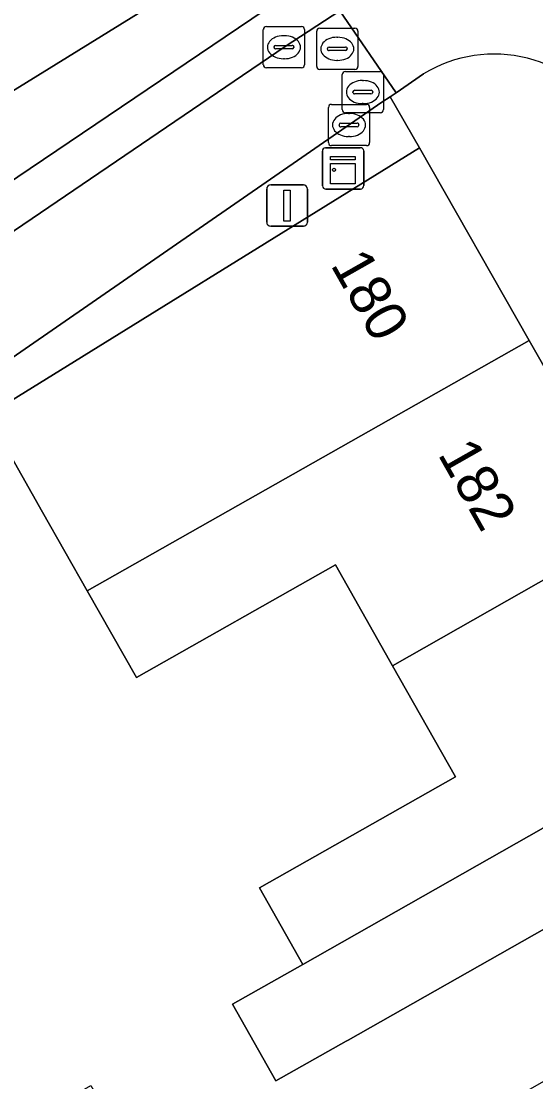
# Model space of a CAD drawing. Extents: x 159888 to 160761, y 384031 to 384750.
# Drawn here: x 160476.49 to 160488.98, y 384308.57 to 384334.29 of the extents above; entities that cross this region are included whole.
import ezdxf

# ---------------------------------------------------------------- set-up
doc = ezdxf.new("R2010")
doc.units = 0
for name, color, linetype in [('IMGEO_Erf', 7, 'Continuous'), ('IMGEO_Kast', 7, 'Continuous'), ('IMGEO_Kolk', 7, 'Continuous'), ('IMGEO_Lichtmast', 7, 'Continuous'), ('IMGEO_Pand', 7, 'Continuous'), ('IMGEO_Pand_nummerreeks', 7, 'Continuous'), ('IMGEO_Rijbaan_lokaal_open', 7, 'Continuous'), ('IMGEO_Rioolput', 7, 'Continuous'), ('IMGEO_Voetpad_open', 7, 'Continuous')]:
    doc.layers.add(name, color=color, linetype=linetype)

msp = doc.modelspace()

# ---------------------------------------------------------------- linework, layer by layer
at = {"layer": 'IMGEO_Erf'}
for points in [[(160456.666, 384356.276), (160458.578, 384353.848), (160460.552, 384351.342), (160461.672, 384352.224), (160468.506, 384356.754), (160471.872, 384351.597), (160475.173, 384346.539), (160478.474, 384341.481), (160481.974, 384336.119), (160475.071, 384331.85), (160475.896, 384330.595), (160472.553, 384328.397), (160468.334, 384334.813), (160471.677, 384337.011), (160468.359, 384342.057), (160465.04, 384347.104), (160461.502, 384344.777), (160458.334, 384349.595), (160454.817, 384346.825), (160452.803, 384349.382), (160452.769, 384349.425), (160446.476, 384344.469), (160444.638, 384346.803)], [(160487.032, 384315.964), (160485.504, 384318.66), (160484.117, 384321.107), (160479.288, 384318.371), (160478.097, 384320.473), (160477.012, 384322.387), (160475.678, 384324.741), (160470.773, 384321.422), (160473.178, 384317.676), (160469.475, 384315.595), (160472.079, 384311.028), (160474.675, 384306.475), (160478.184, 384308.475), (160480.847, 384303.804), (160490.773, 384309.494), (160489.194, 384312.28), (160484.426, 384309.578), (160484.38, 384309.552), (160482.675, 384308.586), (160481.62, 384310.447), (160483.325, 384311.413), (160482.275, 384313.267)]]:
    msp.add_lwpolyline(points, close=True, dxfattribs=at)
msp.add_lwpolyline([(160434.938, 384346.488), (160443.918, 384333.117), (160448.156, 384336.03), (160449.423, 384334.187), (160445.166, 384331.26), (160449.784, 384324.384), (160456.397, 384328.826), (160459.01, 384330.581), (160461.626, 384332.337), (160462.527, 384330.994), (160464.329, 384332.179), (160467.485, 384327.479), (160463.08, 384324.521), (160460.466, 384322.766), (160461.863, 384320.697), (160467.03, 384324.187), (160476.088, 384330.303), (160483.657, 384335.415)], dxfattribs=at)
at = {"layer": 'IMGEO_Kast'}
for p, q in [((160483.88, 384331.223), (160484.721, 384331.223)), ((160484.721, 384331.223), (160483.88, 384331.223)), ((160483.805, 384330.298), (160483.805, 384331.139)), ((160483.805, 384331.139), (160483.805, 384330.298)), ((160484.805, 384331.148), (160484.805, 384330.307)), ((160484.805, 384330.307), (160484.805, 384331.148)), ((160484.73, 384330.223), (160483.889, 384330.223)), ((160483.889, 384330.223), (160484.73, 384330.223))]:
    msp.add_line(p, q, dxfattribs=at)
for points in [[(160484, 384331.013), (160484.6, 384331.013), (160484.6, 384330.928), (160484, 384330.928), (160484, 384331.013)], [(160484, 384330.838), (160484.6, 384330.838), (160484.6, 384330.349), (160484, 384330.349), (160484, 384330.838)]]:
    msp.add_lwpolyline(points, dxfattribs=at)
msp.add_circle((160484.084, 384330.687), 0.0377, dxfattribs=at)
for centre, start, end in [((160483.883, 384331.145), 92.4484, 184.2845), ((160483.883, 384331.145), 92.4484, 184.2845), ((160484.727, 384331.145), 2.4484, 94.2845), ((160484.727, 384331.145), 2.4484, 94.2845), ((160483.883, 384330.301), 182.4484, 274.2845), ((160483.883, 384330.301), 182.4484, 274.2845), ((160484.727, 384330.301), 272.4484, 4.2845), ((160484.727, 384330.301), 272.4484, 4.2845)]:
    msp.add_arc(centre, 0.0779, start, end, dxfattribs=at)
at = {"layer": 'IMGEO_Kolk'}
for p, q in [((160482.369, 384333.237), (160482.369, 384334.089)), ((160482.444, 384334.163), (160483.296, 384334.163)), ((160483.37, 384334.089), (160483.37, 384333.237)), ((160482.857, 384333.943), (160482.882, 384333.943)), ((160482.628, 384333.657), (160482.628, 384333.669)), ((160483.066, 384333.62), (160482.668, 384333.62)), ((160482.671, 384333.706), (160483.069, 384333.706)), ((160483.112, 384333.669), (160483.112, 384333.657)), ((160482.88, 384333.383), (160482.855, 384333.383)), ((160483.296, 384333.163), (160482.444, 384333.163)), ((160484.023, 384332.276), (160484.875, 384332.276)), ((160483.948, 384331.35), (160483.948, 384332.202)), ((160484.436, 384332.056), (160484.461, 384332.056)), ((160484.949, 384332.202), (160484.949, 384331.35)), ((160484.207, 384331.77), (160484.207, 384331.782)), ((160484.645, 384331.733), (160484.247, 384331.733)), ((160484.25, 384331.819), (160484.648, 384331.819)), ((160484.691, 384331.782), (160484.691, 384331.77)), ((160484.459, 384331.496), (160484.434, 384331.496)), ((160484.875, 384331.276), (160484.023, 384331.276))]:
    msp.add_line(p, q, dxfattribs=at)
for points in [[(160482.369, 384333.237), (160482.369, 384334.089)], [(160482.444, 384334.163), (160483.296, 384334.163)], [(160483.37, 384334.089), (160483.37, 384333.237)], [(160483.296, 384333.163), (160482.444, 384333.163)], [(160484.023, 384332.276), (160484.875, 384332.276)], [(160483.948, 384331.35), (160483.948, 384332.202)], [(160484.949, 384332.202), (160484.949, 384331.35)], [(160484.875, 384331.276), (160484.023, 384331.276)]]:
    msp.add_lwpolyline(points, dxfattribs=at)
for centre, radius, start, end in [((160482.446, 384334.087), 0.0765, 91.552, 178.448), ((160482.446, 384334.087), 0.0765, 91.552, 178.448), ((160483.294, 384334.087), 0.0765, 1.552, 88.448), ((160483.294, 384334.087), 0.0765, 1.552, 88.448), ((160482.668, 384333.666), 0.0403, 85.8775, 175.7526), ((160482.665, 384333.656), 0.0366, 178.938, 274.7102), ((160483.069, 384333.663), 0.043, 264.8664, 352.4533), ((160483.073, 384333.668), 0.0386, 1.7309, 96.639), ((160482.446, 384333.239), 0.0765, 181.552, 268.448), ((160482.446, 384333.239), 0.0765, 181.552, 268.448), ((160483.294, 384333.239), 0.0765, 271.552, 358.448), ((160483.294, 384333.239), 0.0765, 271.552, 358.448), ((160484.025, 384332.2), 0.0765, 91.552, 178.448), ((160484.025, 384332.2), 0.0765, 91.552, 178.448), ((160484.873, 384332.2), 0.0765, 1.552, 88.448), ((160484.873, 384332.2), 0.0765, 1.552, 88.448), ((160484.247, 384331.779), 0.0403, 85.8775, 175.7526), ((160484.244, 384331.769), 0.0366, 178.938, 274.7102), ((160484.648, 384331.776), 0.043, 264.8664, 352.4533), ((160484.652, 384331.781), 0.0386, 1.7309, 96.639), ((160484.025, 384331.352), 0.0765, 181.552, 268.448), ((160484.025, 384331.352), 0.0765, 181.552, 268.448), ((160484.873, 384331.352), 0.0765, 271.552, 358.448), ((160484.873, 384331.352), 0.0765, 271.552, 358.448)]:
    msp.add_arc(centre, radius, start, end, dxfattribs=at)
for centre, major_axis, ratio, start_param, end_param in [((160482.856, 384333.663), (-0.387, 0.002), 0.722429, 4.712389, 7.853982), ((160482.881, 384333.663), (-0.39, 0.002), 0.717154, 1.570796, 4.712389), ((160484.435, 384331.776), (-0.387, 0.002), 0.722429, 4.712389, 7.853982), ((160484.46, 384331.776), (-0.39, 0.002), 0.717154, 1.570796, 4.712389)]:
    msp.add_ellipse(centre, major_axis=major_axis, ratio=ratio, start_param=start_param, end_param=end_param, dxfattribs=at)
at = {"layer": 'IMGEO_Lichtmast'}
for p, q in [((160482.45, 384329.421), (160482.45, 384330.221)), ((160482.45, 384330.221), (160482.45, 384329.421)), ((160482.55, 384330.321), (160483.34, 384330.321)), ((160483.34, 384330.321), (160482.55, 384330.321)), ((160483.44, 384330.221), (160483.44, 384329.421)), ((160483.44, 384329.421), (160483.44, 384330.221)), ((160483.34, 384329.321), (160482.55, 384329.321)), ((160482.55, 384329.321), (160483.34, 384329.321))]:
    msp.add_line(p, q, dxfattribs=at)
msp.add_lwpolyline([(160482.87, 384330.196), (160483.02, 384330.196), (160483.02, 384329.446), (160482.87, 384329.446), (160482.87, 384330.196)], dxfattribs=at)
for centre, start, end in [((160482.55, 384330.221), 90, 180), ((160482.55, 384330.221), 90, 180), ((160483.34, 384330.221), 0, 90), ((160483.34, 384330.221), 360, 90), ((160482.55, 384329.421), 180, 270), ((160482.55, 384329.421), 180, 270), ((160483.34, 384329.421), 270, 0), ((160483.34, 384329.421), 270, 0)]:
    msp.add_arc(centre, 0.1, start, end, dxfattribs=at)
at = {"layer": 'IMGEO_Pand'}
for points in [[(160481.974, 384336.119), (160478.474, 384341.481), (160471.677, 384337.011), (160468.334, 384334.813), (160472.553, 384328.397), (160475.896, 384330.595), (160475.071, 384331.85)], [(160488.821, 384326.551), (160486.16, 384331.218), (160475.678, 384324.741), (160477.012, 384322.387), (160478.097, 384320.473)], [(160491.412, 384322.008), (160488.821, 384326.551), (160478.097, 384320.473), (160479.288, 384318.371), (160484.117, 384321.107), (160485.504, 384318.66)], [(160494.003, 384317.464), (160491.412, 384322.008), (160485.504, 384318.66), (160487.032, 384315.964), (160482.275, 384313.267), (160483.325, 384311.413)], [(160496.663, 384312.799), (160494.003, 384317.464), (160483.325, 384311.413), (160481.62, 384310.447), (160482.675, 384308.586), (160484.38, 384309.552), (160484.426, 384309.578), (160489.194, 384312.28), (160490.773, 384309.494), (160492.245, 384310.328)]]:
    msp.add_lwpolyline(points, close=True, dxfattribs=at)
at = {"layer": 'IMGEO_Rijbaan_lokaal_open'}
for points in [[(160485.644, 384335.477), (160484.226, 384334.549), (160485.596, 384332.555), (160486.257, 384333.016)], [(160474.747, 384325.076), (160485.242, 384332.327), (160485.451, 384332.462), (160485.596, 384332.555), (160484.226, 384334.549), (160482.897, 384333.68), (160474.075, 384327.692)]]:
    msp.add_lwpolyline(points, dxfattribs=at)
msp.add_arc((160487.97, 384330.217), 3.281, 29.8057, 121.4605, dxfattribs=at)
at = {"layer": 'IMGEO_Rioolput'}
for p, q in [((160483.664, 384333.198), (160483.664, 384334.05)), ((160483.739, 384334.124), (160484.591, 384334.124)), ((160484.665, 384334.05), (160484.665, 384333.198)), ((160484.152, 384333.904), (160484.177, 384333.904)), ((160483.923, 384333.618), (160483.923, 384333.63)), ((160484.361, 384333.581), (160483.963, 384333.581)), ((160483.966, 384333.667), (160484.364, 384333.667)), ((160484.407, 384333.63), (160484.407, 384333.618)), ((160484.175, 384333.344), (160484.15, 384333.344)), ((160484.591, 384333.124), (160483.739, 384333.124)), ((160484.285, 384332.148), (160484.285, 384333)), ((160484.36, 384333.074), (160485.212, 384333.074)), ((160485.286, 384333), (160485.286, 384332.148)), ((160484.773, 384332.854), (160484.798, 384332.854)), ((160484.544, 384332.568), (160484.544, 384332.58)), ((160484.982, 384332.531), (160484.584, 384332.531)), ((160484.587, 384332.617), (160484.985, 384332.617)), ((160485.028, 384332.58), (160485.028, 384332.568)), ((160484.796, 384332.294), (160484.771, 384332.294)), ((160485.212, 384332.074), (160484.36, 384332.074))]:
    msp.add_line(p, q, dxfattribs=at)
for points in [[(160483.664, 384333.198), (160483.664, 384334.05)], [(160483.739, 384334.124), (160484.591, 384334.124)], [(160484.665, 384334.05), (160484.665, 384333.198)], [(160484.591, 384333.124), (160483.739, 384333.124)], [(160484.285, 384332.148), (160484.285, 384333)], [(160484.36, 384333.074), (160485.212, 384333.074)], [(160485.286, 384333), (160485.286, 384332.148)], [(160485.212, 384332.074), (160484.36, 384332.074)]]:
    msp.add_lwpolyline(points, dxfattribs=at)
for centre, radius, start, end in [((160483.741, 384334.048), 0.0765, 91.552, 178.448), ((160483.741, 384334.048), 0.0765, 91.552, 178.448), ((160484.589, 384334.048), 0.0765, 1.552, 88.448), ((160484.589, 384334.048), 0.0765, 1.552, 88.448), ((160483.963, 384333.627), 0.0403, 85.8775, 175.7526), ((160483.96, 384333.617), 0.0366, 178.938, 274.7102), ((160484.364, 384333.624), 0.043, 264.8664, 352.4533), ((160484.368, 384333.629), 0.0386, 1.7309, 96.639), ((160483.741, 384333.2), 0.0765, 181.552, 268.448), ((160483.741, 384333.2), 0.0765, 181.552, 268.448), ((160484.362, 384332.998), 0.0765, 91.552, 178.448), ((160484.362, 384332.998), 0.0765, 91.552, 178.448), ((160484.589, 384333.2), 0.0765, 271.552, 358.448), ((160484.589, 384333.2), 0.0765, 271.552, 358.448), ((160485.21, 384332.998), 0.0765, 1.552, 88.448), ((160485.21, 384332.998), 0.0765, 1.552, 88.448), ((160484.584, 384332.577), 0.0403, 85.8775, 175.7526), ((160484.581, 384332.567), 0.0366, 178.938, 274.7102), ((160484.985, 384332.574), 0.043, 264.8664, 352.4533), ((160484.989, 384332.579), 0.0386, 1.7309, 96.639), ((160484.362, 384332.15), 0.0765, 181.552, 268.448), ((160484.362, 384332.15), 0.0765, 181.552, 268.448), ((160485.21, 384332.15), 0.0765, 271.552, 358.448), ((160485.21, 384332.15), 0.0765, 271.552, 358.448)]:
    msp.add_arc(centre, radius, start, end, dxfattribs=at)
for centre, major_axis, ratio, start_param, end_param in [((160484.151, 384333.624), (-0.387, 0.002), 0.722429, 4.712389, 7.853982), ((160484.176, 384333.624), (-0.39, 0.002), 0.717154, 1.570796, 4.712389), ((160484.772, 384332.574), (-0.387, 0.002), 0.722429, 4.712389, 7.853982), ((160484.797, 384332.574), (-0.39, 0.002), 0.717154, 1.570796, 4.712389)]:
    msp.add_ellipse(centre, major_axis=major_axis, ratio=ratio, start_param=start_param, end_param=end_param, dxfattribs=at)
at = {"layer": 'IMGEO_Voetpad_open'}
for points in [[(160474.075, 384327.692), (160482.897, 384333.68), (160484.226, 384334.549), (160483.657, 384335.415), (160476.088, 384330.303), (160467.03, 384324.187), (160461.863, 384320.697), (160461.281, 384320.304), (160461.832, 384319.461), (160462.364, 384319.818), (160462.089, 384320.235), (160468.411, 384324.486), (160468.686, 384324.069)], [(160475.678, 384324.741), (160486.16, 384331.218), (160485.451, 384332.462), (160485.242, 384332.327), (160474.747, 384325.076), (160463.235, 384317.314), (160463.685, 384316.625), (160465.155, 384317.62), (160465.616, 384317.932), (160470.773, 384321.422)]]:
    msp.add_lwpolyline(points, close=True, dxfattribs=at)
msp.add_lwpolyline([(160486.257, 384333.016), (160485.596, 384332.555), (160485.451, 384332.462), (160486.16, 384331.218), (160488.821, 384326.551), (160491.412, 384322.008), (160494.003, 384317.464), (160496.663, 384312.799), (160497.383, 384311.495), (160500.525, 384305.972), (160503.615, 384300.54), (160506.705, 384295.108), (160509.796, 384289.676), (160512.886, 384284.244), (160515.577, 384279.514), (160516.041, 384278.668), (160533.512, 384250), (160556.908, 384211.788), (160559.072, 384207.22), (160560.667, 384202.459), (160562.778, 384192.752), (160563.394, 384187.766), (160564.326, 384177.793)], dxfattribs=at)
msp.add_arc((160487.97, 384330.217), 3.281, 29.8057, 121.4605, dxfattribs=at)

# ---------------------------------------------------------------- texts
at = {"layer": 'IMGEO_Pand_nummerreeks'}
for s, p in [('180', (160483.986, 384328.388)), ('182', (160486.589, 384323.794))]:
    msp.add_text(s, height=1, rotation=299.5415, dxfattribs=at).set_placement(p)

doc.saveas('drawing.dxf')
